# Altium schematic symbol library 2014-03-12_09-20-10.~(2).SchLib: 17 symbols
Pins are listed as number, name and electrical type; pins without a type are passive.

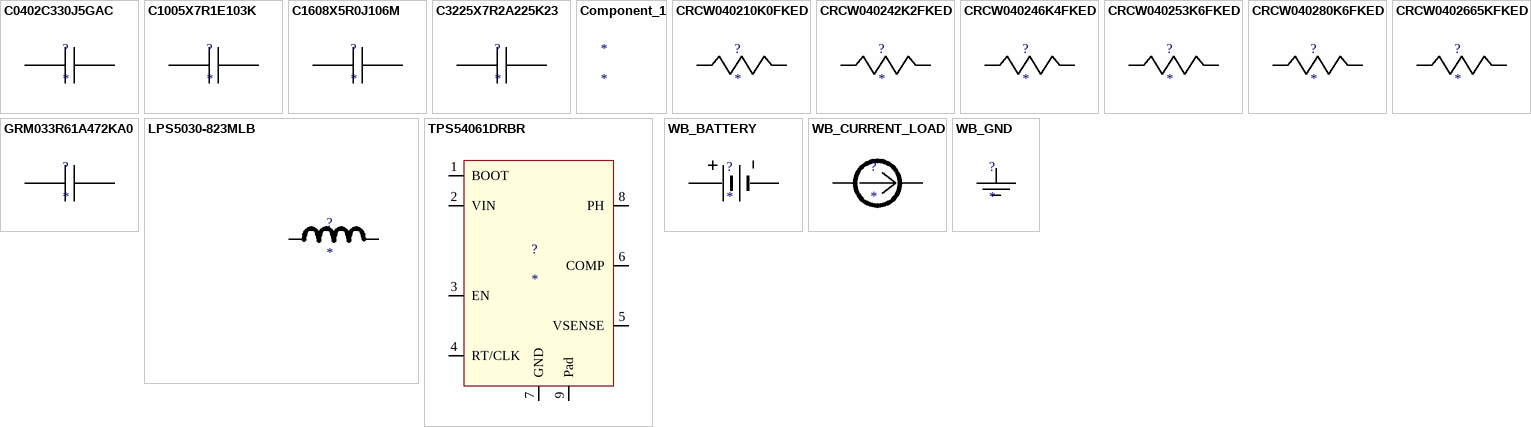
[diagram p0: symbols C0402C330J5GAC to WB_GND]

## C0402C330J5GAC
designator ?
Imported; Manufacturer_Part_Number: C0402C330J5GAC; Vendor: Kemet
footprint 0402
pins: 1, 2

## C1005X7R1E103K
designator ?
Imported; Manufacturer_Part_Number: C1005X7R1E103K; Vendor: TDK
footprint 0402
pins: 1, 2

## C1608X5R0J106M
designator ?
Imported; Manufacturer_Part_Number: C1608X5R0J106M; Vendor: TDK
footprint 0603
pins: 1, 2

## C3225X7R2A225K23
designator ?
Imported; Manufacturer_Part_Number: C3225X7R2A225K230AB; Vendor: TDK
footprint 1210
pins: 1, 2

## Component_1
designator *

## CRCW040210K0FKED
designator ?
Imported; Manufacturer_Part_Number: CRCW040210K0FKED; Vendor: Vishay-Dale
footprint 0402
pins: 1, 2

## CRCW040242K2FKED
designator ?
Imported; Manufacturer_Part_Number: CRCW040242K2FKED; Vendor: Vishay-Dale
footprint 0402
pins: 1, 2

## CRCW040246K4FKED
designator ?
Imported; Manufacturer_Part_Number: CRCW040246K4FKED; Vendor: Vishay-Dale
footprint 0402
pins: 1, 2

## CRCW040253K6FKED
designator ?
Imported; Manufacturer_Part_Number: CRCW040253K6FKED; Vendor: Vishay-Dale
footprint 0402
pins: 1, 2

## CRCW040280K6FKED
designator ?
Imported; Manufacturer_Part_Number: CRCW040280K6FKED; Vendor: Vishay-Dale
footprint 0402
pins: 1, 2

## CRCW0402665KFKED
designator ?
Imported; Manufacturer_Part_Number: CRCW0402665KFKED; Vendor: Vishay-Dale
footprint 0402
pins: 1, 2

## GRM033R61A472KA0
designator ?
Imported; Manufacturer_Part_Number: GRM033R61A472KA01D; Vendor: MuRata
footprint 0201
pins: 1, 2

## LPS5030-823MLB
designator ?
Imported; Manufacturer_Part_Number: LPS5030-823MLB; Vendor: Coilcraft
footprint LPS5030
pins: 1, 2

## TPS54061DRBR
designator ?
Imported; Manufacturer_Part_Number: TPS54061DRBR; Frequency: 1100000.0; Imax: 0.2; Mktg_Package: TPS54061; NSID: TPS54061DRB; Vendor: Texas Instruments
footprint S-PVSON-N8
pins: 1 BOOT, 2 VIN, 3 EN, 4 RT/CLK, 5 VSENSE, 6 COMP, 7 GND, 8 PH, 9 Pad

## WB_BATTERY
designator ?
Imported; Manufacturer_Part_Number: WB_BATTERY; PowerPortType: POWER_GROUND
pins: 1 +, 2 -

## WB_CURRENT_LOAD
designator ?
Imported; Manufacturer_Part_Number: WB_CURRENT_LOAD; PowerPortType: POWER_GROUND
pins: 1 +, 2 -

## WB_GND
designator ?
Imported; Manufacturer_Part_Number: WB_GND; PowerPortType: POWER_GROUND
pins: 1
